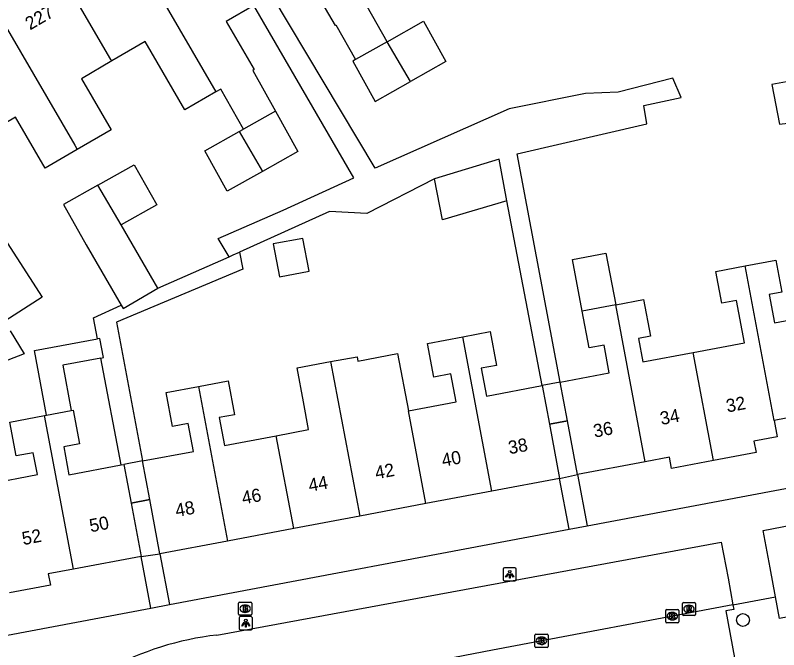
# Model space of a CAD drawing. Extents: x 158352 to 159489, y 383828 to 384597.
# Drawn here: x 158684.3 to 158742.5, y 384058 to 384106.4 of the extents above; entities that cross this region are included whole.
import ezdxf

# ---------------------------------------------------------------- set-up
doc = ezdxf.new("R2010")
doc.units = 0
for name, color, linetype in [('IMGEO_Boom', 7, 'Continuous'), ('IMGEO_Brandkraan', 7, 'Continuous'), ('IMGEO_Kolk', 7, 'Continuous'), ('IMGEO_Lichtpunt', 7, 'Continuous'), ('IMGEO_Pand', 7, 'Continuous'), ('IMGEO_Pand_nummerreeks', 7, 'Continuous'), ('IMGEO_Pand_overbouw', 7, 'Continuous'), ('IMGEO_Rijbaan_lokaal_open', 7, 'Continuous'), ('IMGEO_Rioolput', 7, 'Continuous'), ('IMGEO_Voetpad_open', 7, 'Continuous')]:
    doc.layers.add(name, color=color, linetype=linetype)

msp = doc.modelspace()

# ---------------------------------------------------------------- linework, layer by layer
at = {"layer": 'IMGEO_Boom'}
msp.add_circle((158739.791, 384060.306), 0.489, dxfattribs=at)
at = {"layer": 'IMGEO_Brandkraan'}
for p, q in [((158701.334, 384060.744), (158701.334, 384061.596)), ((158701.409, 384061.67), (158702.261, 384061.67)), ((158701.822, 384061.45), (158701.847, 384061.45)), ((158702.335, 384061.596), (158702.335, 384060.744)), ((158701.845, 384060.89), (158701.82, 384060.89)), ((158702.261, 384060.67), (158701.409, 384060.67))]:
    msp.add_line(p, q, dxfattribs=at)
for points in [[(158701.334, 384060.744), (158701.334, 384061.596)], [(158701.409, 384061.67), (158702.261, 384061.67)], [(158702.335, 384061.596), (158702.335, 384060.744)], [(158701.682, 384061.37), (158701.682, 384060.97), (158701.895, 384060.97)], [(158701.913, 384061.37), (158701.682, 384061.37)], [(158701.861, 384061.289), (158701.807, 384061.289), (158701.807, 384061.213)], [(158701.807, 384061.213), (158701.86, 384061.213)], [(158701.869, 384061.137), (158701.807, 384061.137), (158701.807, 384061.056)], [(158701.807, 384061.056), (158701.869, 384061.056)], [(158702.261, 384060.67), (158701.409, 384060.67)]]:
    msp.add_lwpolyline(points, dxfattribs=at)
for centre, radius, start, end in [((158701.411, 384061.594), 0.0765, 91.55205, 178.44795), ((158701.411, 384061.594), 0.0765, 91.55205, 178.44795), ((158702.259, 384061.594), 0.0765, 1.55205, 88.44795), ((158702.259, 384061.594), 0.0765, 1.55205, 88.44795), ((158701.862, 384061.251), 0.0379, 267.82845, 90.93552), ((158701.87, 384061.096), 0.0404, 269.87594, 90.50774), ((158701.901, 384061.221), 0.251, 268.66757, 293.53466), ((158701.917, 384061.225), 0.145, 59.4692, 91.53667), ((158701.942, 384061.272), 0.0922, 285.51372, 58.15012), ((158701.947, 384061.08), 0.105, 301.31148, 78.98903), ((158701.411, 384060.746), 0.0765, 181.55205, 268.44795), ((158701.411, 384060.746), 0.0765, 181.55205, 268.44795), ((158702.259, 384060.746), 0.0765, 271.55205, 358.44795), ((158702.259, 384060.746), 0.0765, 271.55205, 358.44795)]:
    msp.add_arc(centre, radius, start, end, dxfattribs=at)
for centre, major_axis, ratio, start_param, end_param in [((158701.821, 384061.17), (-0.387, 0.002), 0.722429, 4.712389, 7.853982), ((158701.846, 384061.17), (-0.39, 0.002), 0.717154, 1.570796, 4.712389)]:
    msp.add_ellipse(centre, major_axis=major_axis, ratio=ratio, start_param=start_param, end_param=end_param, dxfattribs=at)
at = {"layer": 'IMGEO_Kolk'}
for p, q in [((158733.902, 384060.174), (158733.902, 384061.026)), ((158733.977, 384061.1), (158734.829, 384061.1)), ((158734.39, 384060.88), (158734.415, 384060.88)), ((158734.903, 384061.026), (158734.903, 384060.174)), ((158734.413, 384060.32), (158734.388, 384060.32)), ((158734.829, 384060.1), (158733.977, 384060.1)), ((158723.933, 384058.296), (158723.933, 384059.148)), ((158724.008, 384059.222), (158724.86, 384059.222)), ((158724.934, 384059.148), (158724.934, 384058.296)), ((158724.421, 384059.002), (158724.446, 384059.002)), ((158724.86, 384058.222), (158724.008, 384058.222)), ((158724.444, 384058.442), (158724.419, 384058.442))]:
    msp.add_line(p, q, dxfattribs=at)
for points in [[(158733.902, 384060.174), (158733.902, 384061.026)], [(158733.977, 384061.1), (158734.829, 384061.1)], [(158734.903, 384061.026), (158734.903, 384060.174)], [(158734.223, 384060.8), (158734.346, 384060.8), (158734.346, 384060.649), (158734.476, 384060.8), (158734.64, 384060.8), (158734.494, 384060.649), (158734.647, 384060.4), (158734.495, 384060.4), (158734.41, 384060.564), (158734.346, 384060.497), (158734.346, 384060.4), (158734.223, 384060.4), (158734.223, 384060.8)], [(158734.829, 384060.1), (158733.977, 384060.1)], [(158723.933, 384058.296), (158723.933, 384059.148)], [(158724.008, 384059.222), (158724.86, 384059.222)], [(158724.934, 384059.148), (158724.934, 384058.296)], [(158724.254, 384058.922), (158724.377, 384058.922), (158724.377, 384058.771), (158724.507, 384058.922), (158724.671, 384058.922), (158724.525, 384058.771), (158724.678, 384058.522), (158724.526, 384058.522), (158724.441, 384058.686), (158724.377, 384058.619), (158724.377, 384058.522), (158724.254, 384058.522), (158724.254, 384058.922)], [(158724.86, 384058.222), (158724.008, 384058.222)]]:
    msp.add_lwpolyline(points, dxfattribs=at)
for centre, start, end in [((158733.979, 384061.024), 91.55205, 178.44795), ((158733.979, 384061.024), 91.55205, 178.44795), ((158734.827, 384061.024), 1.55205, 88.44795), ((158734.827, 384061.024), 1.55205, 88.44795), ((158733.979, 384060.176), 181.55205, 268.44795), ((158733.979, 384060.176), 181.55205, 268.44795), ((158734.827, 384060.176), 271.55205, 358.44795), ((158734.827, 384060.176), 271.55205, 358.44795), ((158724.01, 384059.146), 91.55205, 178.44795), ((158724.01, 384059.146), 91.55205, 178.44795), ((158724.858, 384059.146), 1.55205, 88.44795), ((158724.858, 384059.146), 1.55205, 88.44795), ((158724.01, 384058.298), 181.55205, 268.44795), ((158724.01, 384058.298), 181.55205, 268.44795), ((158724.858, 384058.298), 271.55205, 358.44795), ((158724.858, 384058.298), 271.55205, 358.44795)]:
    msp.add_arc(centre, 0.0765, start, end, dxfattribs=at)
for centre, major_axis, ratio, start_param, end_param in [((158734.389, 384060.6), (-0.387, 0.002), 0.722429, 4.712389, 7.853982), ((158734.414, 384060.6), (-0.39, 0.002), 0.717154, 1.570796, 4.712389), ((158724.42, 384058.722), (-0.387, 0.002), 0.722429, 4.712389, 7.853982), ((158724.445, 384058.722), (-0.39, 0.002), 0.717154, 1.570796, 4.712389)]:
    msp.add_ellipse(centre, major_axis=major_axis, ratio=ratio, start_param=start_param, end_param=end_param, dxfattribs=at)
at = {"layer": 'IMGEO_Lichtpunt'}
for p, q in [((158721.508, 384064.195), (158721.508, 384063.388)), ((158721.508, 384064.195), (158721.508, 384063.388)), ((158722.41, 384064.29), (158721.602, 384064.29)), ((158722.41, 384064.29), (158721.602, 384064.29)), ((158722.504, 384063.388), (158722.504, 384064.195)), ((158722.504, 384063.388), (158722.504, 384064.195)), ((158721.602, 384063.294), (158722.41, 384063.294)), ((158721.602, 384063.294), (158722.41, 384063.294)), ((158701.387, 384060.469), (158701.387, 384059.662)), ((158701.387, 384060.469), (158701.387, 384059.662)), ((158702.289, 384060.564), (158701.481, 384060.564)), ((158702.289, 384060.564), (158701.481, 384060.564)), ((158702.383, 384059.662), (158702.383, 384060.469)), ((158702.383, 384059.662), (158702.383, 384060.469)), ((158701.481, 384059.568), (158702.289, 384059.568)), ((158701.481, 384059.568), (158702.289, 384059.568))]:
    msp.add_line(p, q, dxfattribs=at)
for points in [[(158721.882, 384063.859), (158721.921, 384063.831), (158721.733, 384063.569), (158721.695, 384063.596), (158721.882, 384063.859)], [(158721.984, 384063.811), (158722.031, 384063.811), (158722.031, 384063.489), (158721.984, 384063.489), (158721.984, 384063.811)], [(158722.094, 384063.831), (158722.132, 384063.858), (158722.319, 384063.596), (158722.28, 384063.568), (158722.094, 384063.831)], [(158701.761, 384060.133), (158701.8, 384060.105), (158701.612, 384059.843), (158701.574, 384059.87), (158701.761, 384060.133)], [(158701.863, 384060.085), (158701.91, 384060.085), (158701.91, 384059.763), (158701.863, 384059.763), (158701.863, 384060.085)], [(158701.973, 384060.105), (158702.011, 384060.132), (158702.198, 384059.87), (158702.159, 384059.842), (158701.973, 384060.105)]]:
    msp.add_lwpolyline(points, dxfattribs=at)
for centre in [(158722.007, 384063.993), (158701.886, 384060.267)]:
    msp.add_circle(centre, 0.0994, dxfattribs=at)
for centre, start, end in [((158721.602, 384064.195), 90, 180), ((158721.602, 384064.195), 90, 180), ((158722.41, 384064.195), 0, 90), ((158722.41, 384064.195), 0, 90), ((158721.602, 384063.388), 180, 270), ((158721.602, 384063.388), 180, 270), ((158722.41, 384063.388), 270, 0), ((158722.41, 384063.388), 270, 360), ((158701.481, 384060.469), 90, 180), ((158701.481, 384060.469), 90, 180), ((158702.289, 384060.469), 0, 90), ((158702.289, 384060.469), 0, 90), ((158701.481, 384059.662), 180, 270), ((158701.481, 384059.662), 180, 270), ((158702.289, 384059.662), 270, 0), ((158702.289, 384059.662), 270, 360)]:
    msp.add_arc(centre, 0.0946, start, end, dxfattribs=at)
at = {"layer": 'IMGEO_Pand'}
for points in [[(158693.182, 384111.623), (158699.611, 384100.586)], [(158691.666, 384102.942), (158691.597, 384103.06), (158687.424, 384110.221)], [(158703.886, 384107.932), (158706.481, 384109.443), (158708.686, 384105.658), (158708.758, 384105.7), (158710.247, 384103.055)], [(158682.517, 384107.363), (158688.839, 384096.51), (158689.03, 384096.182)], [(158702.49, 384107.167), (158700.391, 384105.945), (158702.524, 384102.282), (158702.415, 384102.219), (158704.147, 384099.109)], [(158712.659, 384104.412), (158711.15, 384107.093)], [(158712.659, 384104.412), (158715.428, 384105.97), (158717.14, 384102.895), (158714.431, 384101.37)], [(158699.611, 384100.586), (158697.245, 384099.208), (158694.208, 384104.423), (158691.666, 384102.942)], [(158712.659, 384104.412), (158710.247, 384103.055)], [(158714.431, 384101.37), (158712.659, 384104.412)], [(158691.666, 384102.942), (158689.344, 384101.59), (158691.616, 384097.689), (158689.03, 384096.182)], [(158710.247, 384103.055), (158710.041, 384102.939), (158711.753, 384099.863), (158714.431, 384101.37)], [(158746.706, 384102.014), (158743.404, 384101.402), (158742.003, 384101.142), (158742.589, 384098.118), (158743.219, 384098.209), (158743.987, 384098.32), (158746.652, 384098.705), (158749.803, 384097.716), (158749.314, 384100.047)], [(158701.706, 384097.735), (158699.981, 384100.801), (158699.611, 384100.586)], [(158704.147, 384099.109), (158701.706, 384097.735)], [(158704.147, 384099.109), (158705.859, 384096.034), (158703.151, 384094.509)], [(158689.03, 384096.182), (158686.593, 384094.763), (158684.333, 384098.644), (158681.861, 384097.204)], [(158703.151, 384094.509), (158700.472, 384093.002), (158698.76, 384096.078), (158701.379, 384097.551)], [(158701.379, 384097.551), (158701.706, 384097.735)], [(158701.379, 384097.551), (158703.151, 384094.509)], [(158721.797, 384092.275), (158721.197, 384095.441), (158716.283, 384093.959)], [(158690.607, 384093.475), (158693.375, 384095.033), (158695.087, 384091.958), (158692.379, 384090.434)], [(158690.607, 384093.475), (158687.988, 384092.002), (158689.7, 384088.926), (158692.377, 384084.331)], [(158692.379, 384090.434), (158690.607, 384093.475)], [(158721.797, 384092.275), (158716.893, 384090.838), (158716.283, 384093.959)], [(158695.186, 384085.615), (158692.379, 384090.434)], [(158680.813, 384087.719), (158683.463, 384089.422), (158686.354, 384084.927), (158683.506, 384083.096)], [(158706.709, 384086.91), (158706.237, 384089.411), (158703.971, 384088.984), (158704.443, 384086.483), (158706.709, 384086.91)], [(158727.536, 384083.859), (158726.792, 384087.789), (158729.344, 384088.272), (158730.088, 384084.342)], [(158739.964, 384087.32), (158742.296, 384087.762), (158742.761, 384085.308), (158741.787, 384085.123), (158742.196, 384082.969), (158745.979, 384083.688)], [(158735.987, 384080.713), (158739.91, 384081.456), (158739.301, 384084.676), (158738.178, 384084.463), (158737.717, 384086.894), (158739.964, 384087.32)], [(158742.177, 384075.533), (158739.964, 384087.32)], [(158692.377, 384084.331), (158692.53, 384084.068), (158695.186, 384085.615)], [(158730.088, 384084.342), (158732.221, 384084.746), (158732.751, 384081.949), (158731.823, 384081.774), (158732.161, 384079.988), (158735.987, 384080.713)], [(158730.088, 384084.342), (158727.536, 384083.859)], [(158732.336, 384072.372), (158730.088, 384084.342)], [(158725.854, 384078.448), (158729.601, 384079.157), (158729.2, 384081.276), (158728.066, 384081.061), (158727.536, 384083.859)], [(158714.278, 384076.262), (158717.925, 384076.95), (158717.525, 384079.072), (158716.222, 384078.826), (158715.736, 384081.402), (158718.431, 384081.91)], [(158718.431, 384081.91), (158720.524, 384082.305), (158721.01, 384079.729), (158719.84, 384079.508), (158720.241, 384077.387), (158724.473, 384078.187)], [(158720.653, 384070.13), (158718.431, 384081.91)], [(158686.689, 384075.926), (158685.778, 384080.854), (158690.565, 384081.754)], [(158690.841, 384080.286), (158691.024, 384080.32), (158690.748, 384081.788), (158690.565, 384081.754)], [(158737.535, 384072.468), (158735.987, 384080.713)], [(158690.841, 384080.286), (158687.932, 384079.738), (158688.571, 384076.279)], [(158708.353, 384080.01), (158710.37, 384080.389), (158710.432, 384080.06), (158713.454, 384080.63), (158714.278, 384076.262)], [(158704.2, 384074.361), (158706.674, 384074.826), (158706.275, 384076.952), (158705.791, 384079.529), (158708.353, 384080.01)], [(158708.353, 384080.01), (158710.575, 384068.23)], [(158698.275, 384078.11), (158700.549, 384078.538), (158701.034, 384075.963), (158699.849, 384075.74), (158700.248, 384073.618), (158704.2, 384074.361)], [(158727.182, 384071.401), (158726.41, 384075.5), (158725.854, 384078.448)], [(158694.003, 384072.438), (158697.885, 384073.168), (158697.485, 384075.294), (158696.296, 384075.07), (158695.811, 384077.646), (158698.275, 384078.11)], [(158698.275, 384078.11), (158700.497, 384066.33)], [(158724.473, 384078.187), (158725.029, 384075.239), (158725.809, 384071.102)], [(158686.689, 384075.926), (158688.571, 384076.279)], [(158688.571, 384076.279), (158688.729, 384076.309), (158689.213, 384073.734), (158687.999, 384073.506), (158688.398, 384071.384), (158692.375, 384072.132)], [(158715.614, 384069.18), (158714.278, 384076.262)], [(158747.333, 384076.505), (158743.483, 384075.779), (158742.309, 384075.558), (158742.177, 384075.533)], [(158682.295, 384070.696), (158685.997, 384071.393), (158685.682, 384073.069), (158684.372, 384072.823), (158683.888, 384075.399), (158686.532, 384075.896)], [(158686.532, 384075.896), (158686.689, 384075.926)], [(158688.745, 384064.185), (158686.532, 384075.896)], [(158742.177, 384075.533), (158742.411, 384074.285), (158740.63, 384073.949), (158740.794, 384073.082), (158737.535, 384072.468)], [(158705.536, 384067.28), (158704.2, 384074.361)], [(158737.535, 384072.468), (158734.352, 384071.868), (158734.191, 384072.722), (158732.336, 384072.372)], [(158692.375, 384072.132), (158692.581, 384072.171), (158693.137, 384069.223), (158693.903, 384065.158)], [(158695.338, 384065.357), (158694.558, 384069.49), (158694.003, 384072.438)], [(158732.336, 384072.372), (158727.182, 384071.401)], [(158725.809, 384071.102), (158720.653, 384070.13)], [(158720.653, 384070.13), (158715.614, 384069.18)], [(158715.614, 384069.18), (158710.575, 384068.23)], [(158710.575, 384068.23), (158705.536, 384067.28)], [(158705.536, 384067.28), (158700.497, 384066.33)], [(158700.497, 384066.33), (158695.338, 384065.357)], [(158693.903, 384065.158), (158688.745, 384064.185)], [(158688.745, 384064.185), (158686.825, 384063.823), (158686.988, 384062.958), (158683.869, 384062.37)]]:
    msp.add_lwpolyline(points, dxfattribs=at)
at = {"layer": 'IMGEO_Pand_overbouw'}
for points in [[(158724.473, 384078.187), (158725.029, 384075.239), (158726.41, 384075.5), (158725.854, 384078.448)], [(158725.029, 384075.239), (158725.809, 384071.102), (158727.182, 384071.401), (158726.41, 384075.5)], [(158694.558, 384069.49), (158694.003, 384072.438), (158692.581, 384072.171), (158693.137, 384069.223)], [(158693.903, 384065.158), (158695.338, 384065.357), (158694.558, 384069.49), (158693.137, 384069.223)]]:
    msp.add_lwpolyline(points, close=True, dxfattribs=at)
at = {"layer": 'IMGEO_Rijbaan_lokaal_open'}
for points in [[(158742.27, 384062.084), (158741.857, 384064.286), (158741.322, 384067.138), (158743.581, 384067.562), (158744.839, 384060.857)], [(158699.677, 384059.162), (158738.139, 384066.236), (158738.654, 384063.492), (158739.033, 384061.474)], [(158744.839, 384060.857), (158742.579, 384060.433), (158742.27, 384062.084)], [(158739.033, 384061.474), (158720.699, 384058.019), (158698.056, 384053.63)]]:
    msp.add_lwpolyline(points, dxfattribs=at)
msp.add_arc((158702.294, 384036.455), 22.858, 96.57372, 140.39901, dxfattribs=at)
at = {"layer": 'IMGEO_Rioolput'}
for p, q in [((158735.176, 384060.725), (158735.176, 384061.577)), ((158735.251, 384061.651), (158736.103, 384061.651)), ((158736.177, 384061.577), (158736.177, 384060.725)), ((158735.687, 384060.871), (158735.662, 384060.871)), ((158735.664, 384061.431), (158735.689, 384061.431)), ((158736.103, 384060.651), (158735.251, 384060.651))]:
    msp.add_line(p, q, dxfattribs=at)
for points in [[(158735.176, 384060.725), (158735.176, 384061.577)], [(158735.251, 384061.651), (158736.103, 384061.651)], [(158736.177, 384061.577), (158736.177, 384060.725)], [(158735.765, 384061.349), (158735.513, 384061.351), (158735.513, 384060.951)], [(158735.513, 384060.951), (158735.637, 384060.951), (158735.637, 384061.113), (158735.648, 384061.113)], [(158735.691, 384061.27), (158735.637, 384061.27), (158735.637, 384061.189)], [(158735.637, 384061.189), (158735.689, 384061.189)], [(158735.695, 384061.084), (158735.766, 384060.951), (158735.906, 384060.951), (158735.841, 384061.077)], [(158736.103, 384060.651), (158735.251, 384060.651)]]:
    msp.add_lwpolyline(points, dxfattribs=at)
for centre, radius, start, end in [((158735.253, 384061.575), 0.0765, 91.55205, 178.44795), ((158735.253, 384061.575), 0.0765, 91.55205, 178.44795), ((158736.101, 384061.575), 0.0765, 1.55205, 88.44795), ((158736.101, 384061.575), 0.0765, 1.55205, 88.44795), ((158735.647, 384061.06), 0.0533, 26.02933, 88.69889), ((158735.673, 384061.378), 0.19, 274.7715, 282.96867), ((158735.697, 384061.174), 0.0964, 77.00612, 93.18647), ((158735.711, 384061.231), 0.0378, 276.66336, 79.67722), ((158735.764, 384061.239), 0.109, 350.36119, 89.41601), ((158735.762, 384061.239), 0.112, 277.58423, 350.98172), ((158735.746, 384061.024), 0.108, 29.51342, 73.79051), ((158735.253, 384060.727), 0.0765, 181.55205, 268.44795), ((158735.253, 384060.727), 0.0765, 181.55205, 268.44795), ((158736.101, 384060.727), 0.0765, 271.55205, 358.44795), ((158736.101, 384060.727), 0.0765, 271.55205, 358.44795)]:
    msp.add_arc(centre, radius, start, end, dxfattribs=at)
for centre, major_axis, ratio, start_param, end_param in [((158735.663, 384061.151), (-0.387, 0.002), 0.722429, 4.712389, 7.853982), ((158735.688, 384061.151), (-0.39, 0.002), 0.717154, 1.570796, 4.712389)]:
    msp.add_ellipse(centre, major_axis=major_axis, ratio=ratio, start_param=start_param, end_param=end_param, dxfattribs=at)
at = {"layer": 'IMGEO_Voetpad_open'}
for points in [[(158725.854, 384078.448), (158722.571, 384095.855), (158732.47, 384098.16), (158732.24, 384099.536), (158735.083, 384100.15), (158734.439, 384101.63), (158730.28, 384100.554), (158727.797, 384100.464), (158721.977, 384099.298), (158711.747, 384094.756), (158703.886, 384107.932)], [(158700.621, 384088.014), (158699.784, 384089.414), (158704.738, 384091.552), (158710.112, 384094.03), (158702.49, 384107.167)], [(158716.283, 384093.959), (158711.125, 384091.312), (158708.257, 384091.465), (158701.395, 384088.36)], [(158724.473, 384078.187), (158721.797, 384092.275)], [(158701.395, 384088.36), (158701.663, 384087.053), (158692.013, 384083.019), (158694.003, 384072.438)], [(158700.621, 384088.014), (158700.931, 384088.15), (158701.395, 384088.36)], [(158695.186, 384085.615), (158700.621, 384088.014)], [(158690.565, 384081.754), (158690.262, 384083.364), (158692.377, 384084.331)], [(158683.928, 384082.372), (158684.984, 384080.601), (158680.306, 384078.814), (158675.801, 384076.42), (158676.156, 384075.548)], [(158692.375, 384072.132), (158690.841, 384080.286)], [(158727.182, 384071.401), (158727.918, 384067.496)], [(158727.918, 384067.496), (158748.307, 384071.34)], [(158726.538, 384067.236), (158725.809, 384071.102)], [(158726.538, 384067.236), (158727.918, 384067.496)], [(158696.067, 384061.491), (158726.538, 384067.236)], [(158694.645, 384061.222), (158693.903, 384065.158)], [(158695.338, 384065.357), (158696.067, 384061.491)], [(158739.033, 384061.474), (158742.27, 384062.084)], [(158694.645, 384061.222), (158696.067, 384061.491)], [(158739.033, 384061.474), (158739.103, 384061.107), (158738.477, 384060.994), (158739.513, 384055.49), (158723.437, 384052.435), (158722.585, 384056.811)], [(158672.362, 384057.021), (158694.645, 384061.222)]]:
    msp.add_lwpolyline(points, dxfattribs=at)

# ---------------------------------------------------------------- texts
at = {"layer": 'IMGEO_Pand_nummerreeks'}
for s, rotation, p in [('227', 30.22352, (158685.43, 384105.264)), ('32', 10.74869, (158738.608, 384076.128)), ('34', 10.74899, (158733.573, 384075.172)), ('36', 10.67344, (158728.48, 384074.21)), ('38', 10.6772, (158721.993, 384072.947)), ('40', 10.6772, (158716.915, 384071.99)), ('42', 10.6772, (158711.83, 384071.031)), ('44', 10.67993, (158706.756, 384070.074)), ('46', 10.6772, (158701.676, 384069.117)), ('48', 10.6772, (158696.601, 384068.16)), ('50', 10.77161, (158690.057, 384066.992)), ('52', 10.77301, (158684.917, 384066.014))]:
    msp.add_text(s, height=1, rotation=rotation, dxfattribs=at).set_placement(p)

doc.saveas('drawing.dxf')
